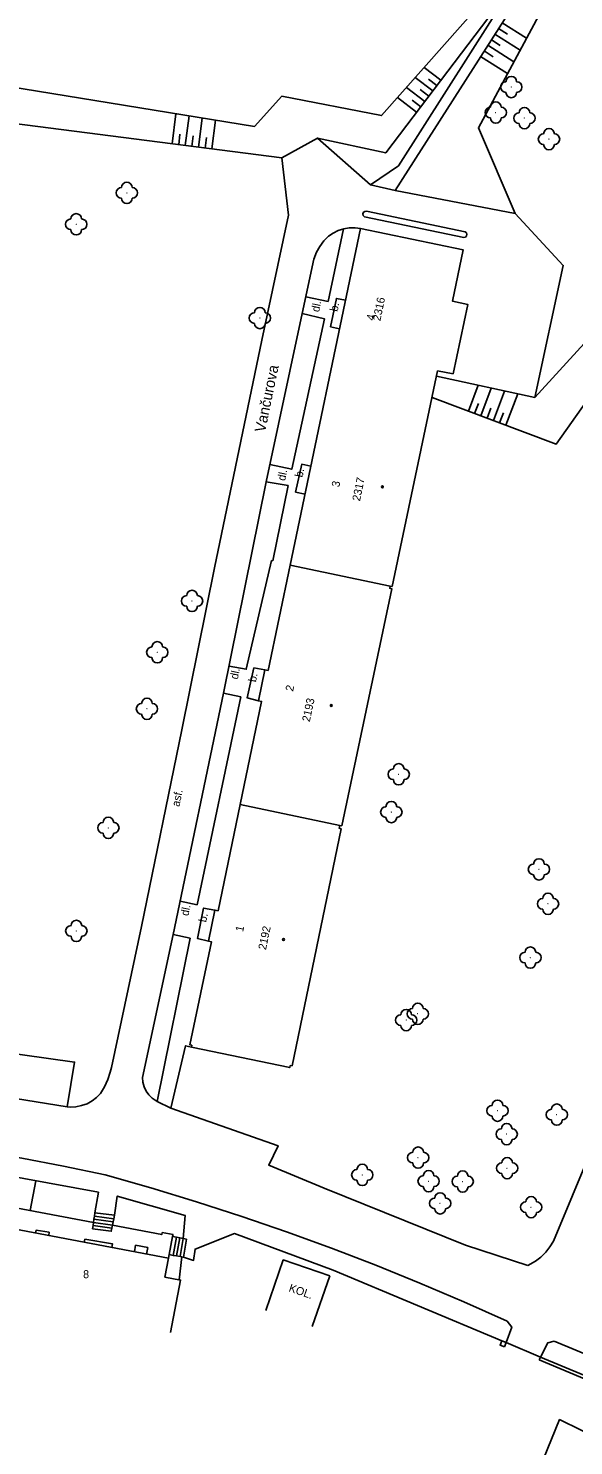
# Model space of a CAD drawing. Extents: x -584400 to -581602, y -1210894 to -1208793.
# Drawn here: x -582745.5 to -582694.5, y -1210202.4 to -1210069.5 of the extents above; entities that cross this region are included whole.
import ezdxf

# ---------------------------------------------------------------- set-up
doc = ezdxf.new("R2010")
doc.units = 0
for name, color, linetype in [('BUDOVY_MĚŘ', 7, 'Continuous'), ('NÁZVY_ULIC_TOK_SMĚR', 7, 'Continuous'), ('POMOC_POPIS', 7, 'Continuous'), ('ROZHRANÍ_PLOCH', 7, 'Continuous'), ('VÝŠKOPIS', 7, 'Continuous'), ('ZELEŇ', 7, 'Continuous'), ('ZN_BUDOV', 7, 'Continuous'), ('ZN_DOPLŇKOVÉ', 7, 'Continuous'), ('Č_POPIS_EVID', 7, 'Continuous')]:
    doc.layers.add(name, color=color, linetype=linetype)

msp = doc.modelspace()

# ---------------------------------------------------------------- linework, layer by layer
at = {"layer": 'BUDOVY_MĚŘ'}
for points in [[(-582721.01, -1210119.86), (-582714.42, -1210088.3), (-582704.81, -1210090.31), (-582705.81, -1210095.11), (-582704.38, -1210095.41), (-582705.76, -1210101.93)], [(-582707.21, -1210101.64), (-582711.46, -1210121.87)], [(-582707.21, -1210101.64), (-582705.76, -1210101.93)], [(-582723.07, -1210129.73), (-582721.01, -1210119.86)], [(-582721.01, -1210119.86), (-582711.65, -1210121.83)], [(-582711.65, -1210121.83), (-582711.69, -1210122.02), (-582711.5, -1210122.06), (-582716.18, -1210144.29)], [(-582711.65, -1210121.83), (-582711.46, -1210121.87)], [(-582723.07, -1210129.73), (-582723.37, -1210129.67), (-582723.98, -1210132.56)], [(-582725.69, -1210142.29), (-582723.68, -1210132.62), (-582723.98, -1210132.56)], [(-582727.76, -1210152.25), (-582725.69, -1210142.29)], [(-582725.69, -1210142.29), (-582716.36, -1210144.25)], [(-582716.24, -1210144.56), (-582716.41, -1210144.52), (-582716.36, -1210144.25)], [(-582716.36, -1210144.25), (-582716.18, -1210144.29)], [(-582716.24, -1210144.56), (-582720.83, -1210166.8)], [(-582727.76, -1210152.25), (-582728.06, -1210152.19), (-582728.67, -1210155.11)], [(-582730.21, -1210164.86), (-582730.39, -1210164.82), (-582728.37, -1210155.17), (-582728.67, -1210155.11)], [(-582730.21, -1210164.86), (-582730.24, -1210165.05)], [(-582721.01, -1210166.76), (-582721.05, -1210166.95), (-582730.24, -1210165.05)], [(-582721.01, -1210166.76), (-582720.83, -1210166.8)], [(-582760.08, -1210191.37), (-582764.99, -1210190.45), (-582763.83, -1210184.27), (-582763.19, -1210180.86), (-582761.73, -1210181.09), (-582761.38, -1210179.31), (-582732.4, -1210184.82)], [(-582732.2, -1210191.78), (-582731.27, -1210186.87), (-582732.74, -1210186.59), (-582732.4, -1210184.82)], [(-582723.28, -1210189.71), (-582721.66, -1210184.98), (-582717.31, -1210186.48)], [(-582718.94, -1210191.21), (-582717.31, -1210186.48)], [(-582686.65, -1210213.72), (-582699.21, -1210208.31), (-582695.79, -1210199.95), (-582691.73, -1210201.95)]]:
    msp.add_lwpolyline(points, dxfattribs=at)
at = {"layer": 'ROZHRANÍ_PLOCH'}
for points in [[(-582711.18, -1210084.74), (-582697.8, -1210063.73)], [(-582699.85, -1210065.08), (-582710.87, -1210082.42), (-582713.5, -1210084.2)], [(-582718.45, -1210079.82), (-582721.79, -1210081.68)], [(-582713.5, -1210084.2), (-582718.45, -1210079.82)], [(-582721.79, -1210081.68), (-582721.17, -1210087.06), (-582723.67, -1210098.77), (-582728.09, -1210120.1), (-582731.15, -1210135.28), (-582734.94, -1210153.72)], [(-582711.18, -1210084.74), (-582713.5, -1210084.2)], [(-582699.96, -1210086.9), (-582711.18, -1210084.74)], [(-582713.88, -1210086.66), (-582714.03, -1210086.69), (-582714.15, -1210086.78), (-582714.2, -1210086.93), (-582714.17, -1210087.07), (-582714.05, -1210087.21)], [(-582713.88, -1210086.66), (-582704.63, -1210088.62), (-582704.51, -1210088.71), (-582704.47, -1210088.85), (-582704.5, -1210088.99), (-582704.6, -1210089.1), (-582704.76, -1210089.13), (-582714.05, -1210087.21)], [(-582699.96, -1210086.9), (-582695.45, -1210091.76), (-582698.11, -1210104.15)], [(-582714.42, -1210088.3), (-582714.94, -1210088.23), (-582715.48, -1210088.23), (-582716, -1210088.32), (-582716.51, -1210088.48), (-582716.99, -1210088.72), (-582717.42, -1210089.03), (-582717.86, -1210089.45), (-582718.23, -1210089.97), (-582718.54, -1210090.53), (-582718.79, -1210091.18), (-582719.9, -1210096.27)], [(-582716.03, -1210088.32), (-582717.46, -1210095.13), (-582719.56, -1210094.69)], [(-582715.82, -1210095.03), (-582716.68, -1210094.85), (-582717.24, -1210097.51)], [(-582719.9, -1210096.27), (-582723.25, -1210112.05)], [(-582719.9, -1210096.27), (-582717.8, -1210096.75), (-582720.87, -1210110.86), (-582722.9, -1210110.42)], [(-582716.38, -1210097.69), (-582717.24, -1210097.51)], [(-582707.31, -1210102.13), (-582698.11, -1210104.15)], [(-582719.07, -1210110.58), (-582719.92, -1210110.4), (-582720.5, -1210113.02)], [(-582723.25, -1210112.05), (-582727.25, -1210131.86)], [(-582723.25, -1210112.05), (-582721.2, -1210112.39), (-582722.65, -1210119.44), (-582722.77, -1210119.41)], [(-582668.26, -1210112.29), (-582670.89, -1210118.7), (-582669.83, -1210119.14), (-582672.92, -1210126.61), (-582679.78, -1210143.27), (-582687.15, -1210161.08), (-582696.36, -1210183.21), (-582696.69, -1210183.76), (-582697.09, -1210184.26), (-582697.54, -1210184.72), (-582698.05, -1210185.11), (-582698.76, -1210185.51)], [(-582719.62, -1210113.2), (-582720.5, -1210113.02)], [(-582726.73, -1210129.31), (-582725.13, -1210129.61), (-582722.77, -1210119.41)], [(-582723.37, -1210129.67), (-582724.4, -1210129.48), (-582725.04, -1210132.29), (-582723.98, -1210132.56)], [(-582727.25, -1210131.86), (-582731.97, -1210154.49)], [(-582725.62, -1210132.2), (-582729.72, -1210151.69), (-582731.32, -1210151.35)], [(-582725.62, -1210132.2), (-582727.25, -1210131.86)], [(-582728.06, -1210152.19), (-582729.12, -1210152), (-582729.69, -1210154.85), (-582728.67, -1210155.11)], [(-582738.76, -1210169.38), (-582738.38, -1210168.75), (-582738.08, -1210168.08), (-582737.85, -1210167.38), (-582737.75, -1210166.94), (-582734.94, -1210153.72)], [(-582731.97, -1210154.49), (-582734.83, -1210167.88), (-582734.8, -1210168.32), (-582734.69, -1210168.75), (-582734.5, -1210169.15), (-582734.25, -1210169.51), (-582733.93, -1210169.82), (-582733.47, -1210170.13)], [(-582733.47, -1210170.13), (-582730.38, -1210154.82), (-582731.97, -1210154.49)], [(-582764.23, -1210167.07), (-582763.58, -1210163.29), (-582741.19, -1210166.44), (-582741.89, -1210170.63)], [(-582730.24, -1210165.05), (-582730.8, -1210164.9), (-582732.19, -1210170.75)], [(-582764.23, -1210167.07), (-582753.52, -1210168.77), (-582741.89, -1210170.63)], [(-582738.76, -1210169.38), (-582739.13, -1210169.76), (-582739.56, -1210170.08), (-582740.03, -1210170.34), (-582740.54, -1210170.52), (-582741.07, -1210170.62), (-582741.6, -1210170.65), (-582741.89, -1210170.63)], [(-582733.47, -1210170.13), (-582732.19, -1210170.75)], [(-582732.19, -1210170.75), (-582722.15, -1210174.27), (-582723.01, -1210176.11), (-582717.82, -1210178.24), (-582704.6, -1210183.59), (-582698.76, -1210185.51)], [(-582738.34, -1210177), (-582742.24, -1210176.18), (-582746.14, -1210175.44), (-582750.07, -1210174.78), (-582754, -1210174.19), (-582757.95, -1210173.69), (-582761.9, -1210173.26), (-582765.87, -1210172.92), (-582770.88, -1210172.6)], [(-582753.28, -1210177.38), (-582752.97, -1210176.08), (-582738.97, -1210178.64), (-582739.29, -1210180.56)], [(-582738.34, -1210177), (-582734.06, -1210178.22), (-582729.79, -1210179.52), (-582725.55, -1210180.9), (-582721.34, -1210182.35), (-582717.15, -1210183.88), (-582712.99, -1210185.48), (-582708.86, -1210187.16), (-582704.76, -1210188.91), (-582700.7, -1210190.73), (-582700.25, -1210191.27), (-582700.78, -1210192.71)], [(-582753.35, -1210178.86), (-582739.42, -1210181.46)], [(-582737.45, -1210180.79), (-582737.2, -1210178.99), (-582730.83, -1210180.83), (-582731.03, -1210182.98)], [(-582739.47, -1210181.76), (-582739.42, -1210181.46)], [(-582739.42, -1210181.46), (-582739.38, -1210181.16)], [(-582737.64, -1210181.71), (-582739.42, -1210181.46)], [(-582739.38, -1210181.16), (-582739.34, -1210180.87)], [(-582737.58, -1210181.42), (-582739.38, -1210181.16)], [(-582739.34, -1210180.87), (-582739.29, -1210180.56)], [(-582737.52, -1210181.12), (-582739.34, -1210180.87)], [(-582739.29, -1210180.56), (-582737.45, -1210180.79)], [(-582737.58, -1210181.42), (-582737.64, -1210181.71)], [(-582737.52, -1210181.12), (-582737.58, -1210181.42)], [(-582737.45, -1210180.79), (-582737.52, -1210181.12)], [(-582744.84, -1210182.45), (-582744.79, -1210182.19), (-582743.56, -1210182.38)], [(-582743.62, -1210182.69), (-582743.56, -1210182.38)], [(-582737.7, -1210182), (-582737.76, -1210182.3), (-582739.51, -1210182.06), (-582739.47, -1210181.76)], [(-582737.7, -1210182), (-582739.47, -1210181.76)], [(-582737.64, -1210181.71), (-582737.7, -1210182)], [(-582737.64, -1210181.71), (-582733.04, -1210182.61), (-582733, -1210182.4)], [(-582731.98, -1210182.59), (-582733, -1210182.4)], [(-582732.02, -1210182.79), (-582732.34, -1210184.48)], [(-582731.98, -1210182.59), (-582732.02, -1210182.79)], [(-582732.02, -1210182.79), (-582731.66, -1210182.86)], [(-582731.01, -1210184.73), (-582730.05, -1210185.03), (-582729.91, -1210183.97), (-582726.22, -1210182.51), (-582716.99, -1210185.95), (-582701.2, -1210192.55)], [(-582740.3, -1210183.32), (-582740.25, -1210183.03)], [(-582737.71, -1210183.81), (-582737.64, -1210183.48), (-582740.25, -1210183.03)], [(-582735.6, -1210184.21), (-582735.49, -1210183.61), (-582734.33, -1210183.83)], [(-582734.45, -1210184.43), (-582734.33, -1210183.83)], [(-582731.95, -1210184.55), (-582731.66, -1210182.86)], [(-582731.66, -1210182.86), (-582731.35, -1210182.92)], [(-582731.64, -1210184.61), (-582731.35, -1210182.92)], [(-582731.35, -1210182.92), (-582731.03, -1210182.98)], [(-582731.32, -1210184.67), (-582731.03, -1210182.98)], [(-582731.03, -1210182.98), (-582730.72, -1210183.04)], [(-582731.01, -1210184.73), (-582730.72, -1210183.04)], [(-582732.34, -1210184.48), (-582732.4, -1210184.82)], [(-582732.34, -1210184.48), (-582731.95, -1210184.55)], [(-582731.95, -1210184.55), (-582731.64, -1210184.61)], [(-582731.64, -1210184.61), (-582731.32, -1210184.67)], [(-582731.41, -1210186.84), (-582731.16, -1210184.7)], [(-582731.32, -1210184.67), (-582731.16, -1210184.7)], [(-582731.16, -1210184.7), (-582731.01, -1210184.73)], [(-582697.59, -1210194.08), (-582696.88, -1210192.74), (-582696.31, -1210192.59)], [(-582696.89, -1210247.66), (-582695.96, -1210245.41), (-582695.08, -1210243.28), (-582693.8, -1210240.33), (-582685.39, -1210220.2), (-582680.46, -1210208.47), (-582678.19, -1210202.95), (-582678.05, -1210202.51), (-582677.99, -1210202.06), (-582678.01, -1210201.6), (-582678.11, -1210201.16), (-582678.29, -1210200.74), (-582678.54, -1210200.36), (-582678.85, -1210200.02), (-582679.21, -1210199.75), (-582679.7, -1210199.51), (-582696.31, -1210192.59)]]:
    msp.add_lwpolyline(points, dxfattribs=at)
at = {"layer": 'VÝŠKOPIS'}
for points in [[(-582691.06, -1210062.13), (-582695.71, -1210064.53), (-582703.38, -1210078.85), (-582699.96, -1210086.9)], [(-582721.8, -1210075.88), (-582712.46, -1210077.71), (-582700.9, -1210064.65)], [(-582699.85, -1210065.08), (-582712.07, -1210081.21), (-582718.45, -1210079.82)], [(-582700.66, -1210070.08), (-582701.5, -1210069.54)], [(-582698.89, -1210070.47), (-582701.17, -1210069.01)], [(-582700.07, -1210072.68), (-582702.51, -1210071.12)], [(-582701.34, -1210071.13), (-582702.17, -1210070.6)], [(-582699.48, -1210071.57), (-582701.84, -1210070.07)], [(-582700.66, -1210073.78), (-582703.18, -1210072.18)], [(-582702.01, -1210072.19), (-582702.85, -1210071.65)], [(-582708.47, -1210073.2), (-582706.9, -1210074.39)], [(-582721.8, -1210075.88), (-582724.36, -1210078.74), (-582748.71, -1210074.77), (-582764.95, -1210074.05), (-582767.65, -1210076.52)], [(-582710.13, -1210075.08), (-582708.41, -1210076.38)], [(-582709.3, -1210074.14), (-582707.66, -1210075.39)], [(-582708.07, -1210074.29), (-582707.28, -1210074.89)], [(-582710.96, -1210076.02), (-582709.17, -1210077.38)], [(-582709.58, -1210076.28), (-582708.79, -1210076.88)], [(-582708.83, -1210075.28), (-582708.03, -1210075.89)], [(-582731.71, -1210077.54), (-582732.07, -1210080.36)], [(-582730.48, -1210077.74), (-582730.83, -1210080.52)], [(-582767.49, -1210078.19), (-582749.3, -1210078.15), (-582721.79, -1210081.68)], [(-582729.24, -1210077.94), (-582729.59, -1210080.68)], [(-582728.01, -1210078.14), (-582728.35, -1210080.84)], [(-582731.33, -1210079.46), (-582731.45, -1210080.44)], [(-582730.09, -1210079.61), (-582730.21, -1210080.6)], [(-582728.85, -1210079.77), (-582728.97, -1210080.76)], [(-582698.11, -1210104.15), (-582693.5, -1210099.09), (-582676.16, -1210101.62), (-582663.83, -1210079.72)], [(-582660.6, -1210080.93), (-582672.67, -1210107.06), (-582692.32, -1210103.17), (-582696.1, -1210108.51), (-582707.73, -1210104.13)], [(-582703.42, -1210102.99), (-582704.33, -1210105.41)], [(-582702.18, -1210103.26), (-582703.16, -1210105.85)], [(-582700.95, -1210103.53), (-582701.99, -1210106.29)], [(-582699.71, -1210103.8), (-582700.82, -1210106.73)], [(-582703.39, -1210104.7), (-582703.75, -1210105.63)], [(-582702.22, -1210105.14), (-582702.57, -1210106.07)], [(-582701.05, -1210105.58), (-582701.41, -1210106.51)], [(-582744.82, -1210177.57), (-582745.34, -1210180.36)]]:
    msp.add_lwpolyline(points, dxfattribs=at)
at = {"layer": 'ZELEŇ'}
for centre in [(-582700.31, -1210075.04), (-582701.76, -1210077.43), (-582699.08, -1210077.95), (-582696.78, -1210079.92), (-582736.3, -1210084.96), (-582741.04, -1210087.9), (-582723.85, -1210096.69), (-582730.2, -1210123.21), (-582733.45, -1210128.02), (-582734.42, -1210133.32), (-582710.85, -1210139.46), (-582711.54, -1210143), (-582738.03, -1210144.48), (-582697.72, -1210148.37), (-582696.87, -1210151.6), (-582741.03, -1210154.14), (-582698.52, -1210156.64), (-582710.15, -1210162.5), (-582709.06, -1210161.91), (-582701.6, -1210170.99), (-582696.05, -1210171.36), (-582700.74, -1210173.19), (-582709.03, -1210175.39), (-582714.26, -1210177.01), (-582700.7, -1210176.38), (-582708.05, -1210177.6), (-582704.86, -1210177.63), (-582706.97, -1210179.68), (-582698.45, -1210180.04)]:
    msp.add_circle(centre, 0.0005, dxfattribs=at)
for centre, start, end in [((-582700.81, -1210075.04), 90, 270), ((-582700.31, -1210074.54), 0, 180), ((-582699.81, -1210075.04), 270, 90), ((-582701.76, -1210076.93), 0, 180), ((-582700.31, -1210075.54), 180, 360), ((-582702.26, -1210077.43), 90, 270), ((-582701.26, -1210077.43), 270, 90), ((-582699.58, -1210077.95), 90, 270), ((-582699.08, -1210077.45), 0, 180), ((-582698.58, -1210077.95), 270, 90), ((-582701.76, -1210077.93), 180, 360), ((-582699.08, -1210078.45), 180, 360), ((-582696.78, -1210079.42), 0, 180), ((-582697.28, -1210079.92), 90, 270), ((-582696.78, -1210080.42), 180, 360), ((-582696.28, -1210079.92), 270, 90), ((-582736.8, -1210084.96), 90, 270), ((-582736.3, -1210084.46), 0, 180), ((-582735.8, -1210084.96), 270, 90), ((-582736.3, -1210085.46), 180, 360), ((-582741.04, -1210087.4), 0, 180), ((-582741.54, -1210087.9), 90, 270), ((-582741.04, -1210088.4), 180, 360), ((-582740.54, -1210087.9), 270, 90), ((-582724.35, -1210096.69), 90, 270), ((-582723.85, -1210096.19), 0, 180), ((-582723.35, -1210096.69), 270, 90), ((-582723.85, -1210097.19), 180, 360), ((-582730.7, -1210123.21), 90, 270), ((-582730.2, -1210122.71), 0, 180), ((-582729.7, -1210123.21), 270, 90), ((-582730.2, -1210123.71), 180, 360), ((-582733.45, -1210127.52), 0, 180), ((-582733.95, -1210128.02), 90, 270), ((-582732.95, -1210128.02), 270, 90), ((-582733.45, -1210128.52), 180, 360), ((-582734.42, -1210132.82), 0, 180), ((-582734.92, -1210133.32), 90, 270), ((-582733.92, -1210133.32), 270, 90), ((-582734.42, -1210133.82), 180, 360), ((-582711.35, -1210139.46), 90, 270), ((-582710.85, -1210138.96), 0, 180), ((-582710.35, -1210139.46), 270, 90), ((-582710.85, -1210139.96), 180, 360), ((-582712.04, -1210143), 90, 270), ((-582711.54, -1210142.5), 0, 180), ((-582711.04, -1210143), 270, 90), ((-582738.53, -1210144.48), 90, 270), ((-582738.03, -1210143.98), 0, 180), ((-582737.53, -1210144.48), 270, 90), ((-582711.54, -1210143.5), 180, 360), ((-582738.03, -1210144.98), 180, 360), ((-582698.22, -1210148.37), 90, 270), ((-582697.72, -1210147.87), 0, 180), ((-582697.22, -1210148.37), 270, 90), ((-582697.72, -1210148.87), 180, 360), ((-582696.87, -1210151.1), 0, 180), ((-582697.37, -1210151.6), 90, 270), ((-582696.87, -1210152.1), 180, 360), ((-582696.37, -1210151.6), 270, 90), ((-582741.03, -1210153.64), 0, 180), ((-582741.53, -1210154.14), 90, 270), ((-582741.03, -1210154.64), 180, 360), ((-582740.53, -1210154.14), 270, 90), ((-582699.02, -1210156.64), 90, 270), ((-582698.52, -1210156.14), 0, 180), ((-582698.02, -1210156.64), 270, 90), ((-582698.52, -1210157.14), 180, 360), ((-582710.15, -1210162), 0, 180), ((-582709.56, -1210161.91), 90, 270), ((-582709.06, -1210161.41), 0, 180), ((-582708.56, -1210161.91), 270, 90), ((-582710.65, -1210162.5), 90, 270), ((-582709.65, -1210162.5), 270, 90), ((-582709.06, -1210162.41), 180, 360), ((-582710.15, -1210163), 180, 360), ((-582702.1, -1210170.99), 90, 270), ((-582701.6, -1210170.49), 0, 180), ((-582701.1, -1210170.99), 270, 90), ((-582696.55, -1210171.36), 90, 270), ((-582696.05, -1210170.86), 0, 180), ((-582695.55, -1210171.36), 270, 90), ((-582701.6, -1210171.49), 180, 360), ((-582700.74, -1210172.69), 0, 180), ((-582696.05, -1210171.86), 180, 360), ((-582701.24, -1210173.19), 90, 270), ((-582700.24, -1210173.19), 270, 90), ((-582709.03, -1210174.89), 0, 180), ((-582700.74, -1210173.69), 180, 360), ((-582714.26, -1210176.51), 0, 180), ((-582709.53, -1210175.39), 90, 270), ((-582709.03, -1210175.89), 180, 360), ((-582708.53, -1210175.39), 270, 90), ((-582701.2, -1210176.38), 90, 270), ((-582700.7, -1210175.88), 0, 180), ((-582700.2, -1210176.38), 270, 90), ((-582714.76, -1210177.01), 90, 270), ((-582714.26, -1210177.51), 180, 360), ((-582713.76, -1210177.01), 270, 90), ((-582708.55, -1210177.6), 90, 270), ((-582708.05, -1210177.1), 0, 180), ((-582707.55, -1210177.6), 270, 90), ((-582705.36, -1210177.63), 90, 270), ((-582704.86, -1210177.13), 0, 180), ((-582704.36, -1210177.63), 270, 90), ((-582700.7, -1210176.88), 180, 360), ((-582708.05, -1210178.1), 180, 360), ((-582706.97, -1210179.18), 0, 180), ((-582704.86, -1210178.13), 180, 360), ((-582707.47, -1210179.68), 90, 270), ((-582706.97, -1210180.18), 180, 360), ((-582706.47, -1210179.68), 270, 90), ((-582698.95, -1210180.04), 90, 270), ((-582698.45, -1210179.54), 0, 180), ((-582697.95, -1210180.04), 270, 90), ((-582698.45, -1210180.54), 180, 360)]:
    msp.add_arc(centre, 0.5, start, end, dxfattribs=at)
at = {"layer": 'ZN_BUDOV'}
for centre in [(-582712.38, -1210112.52), (-582717.16, -1210133.01), (-582721.63, -1210154.95)]:
    msp.add_circle(centre, 0.0875, dxfattribs=at)
at = {"layer": 'ZN_DOPLŇKOVÉ'}
for points in [[(-582701.2, -1210192.55), (-582701.36, -1210192.97), (-582700.94, -1210193.13)], [(-582701.2, -1210192.55), (-582700.78, -1210192.71), (-582700.94, -1210193.13)], [(-582697.59, -1210194.08), (-582700.78, -1210192.71)], [(-582697.59, -1210194.08), (-582697.71, -1210194.36)], [(-582689.96, -1210197.6), (-582697.71, -1210194.36)], [(-582697.59, -1210194.08), (-582689.84, -1210197.32)]]:
    msp.add_lwpolyline(points, dxfattribs=at)

# ---------------------------------------------------------------- texts
at = {"layer": 'NÁZVY_ULIC_TOK_SMĚR'}
msp.add_text('Vančurova', height=1, rotation=78.3388, dxfattribs=at).set_placement((-582723.37, -1210107.46))
at = {"layer": 'POMOC_POPIS'}
for s, rotation, p in [('dl.', 78.3388, (-582718.31, -1210096.17)), ('b.', 78.3388, (-582716.58, -1210096.13)), ('dl.', 78.3388, (-582721.49, -1210111.99)), ('b.', 78.3388, (-582719.86, -1210111.67)), ('dl.', 78.3388, (-582725.92, -1210130.6)), ('b.', 78.3388, (-582724.22, -1210130.86)), ('asf.', 78.3388, (-582731.39, -1210142.54)), ('dl.', 78.3388, (-582730.54, -1210152.78)), ('b.', 78.3388, (-582728.88, -1210153.37)), ('KOL.', 341.0403, (-582721.2, -1210187.91))]:
    msp.add_text(s, height=0.75, rotation=rotation, dxfattribs=at).set_placement(p)
at = {"layer": 'Č_POPIS_EVID'}
for s, rotation, p in [('2316', 78.2063, (-582712.57, -1210097.01)), ('4', 78.2063, (-582713.16, -1210096.97)), ('3', 78.2063, (-582716.42, -1210112.59)), ('2317', 78.2063, (-582714.48, -1210113.9)), ('2', 78.0414, (-582720.74, -1210131.73)), ('2193', 78.0624, (-582719.18, -1210134.59)), ('1', 78.2079, (-582725.42, -1210154.27)), ('2192', 78.1886, (-582723.28, -1210155.96)), ('8', 359.4255, (-582740.4, -1210186.69))]:
    msp.add_text(s, height=0.75, rotation=rotation, dxfattribs=at).set_placement(p)

doc.saveas('drawing.dxf')
